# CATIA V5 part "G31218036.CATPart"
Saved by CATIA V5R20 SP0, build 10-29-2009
Part number: G31218036
Revision: 10
Definition: design
Nomenclature: G31218036
Source: made
Description: NOT SPECIFIED
Bounding box of the stored display mesh (mm): x -8 to 36, y -15.5 to 15.5, z -15.5 to 15.5
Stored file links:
  C:\Users\Raffaele\Desktop\3D X SITO CF\BOLEX\23-BUSH REF 312\G31218036.CATPart

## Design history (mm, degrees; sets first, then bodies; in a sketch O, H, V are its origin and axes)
Body1 "MANIFOLD_SOLID_BREP #10171" (main body)
  Solid1: solid without history
Body2 "MANIFOLD_SOLID_BREP #10314"
  Solid2: solid without history
Body3 "MANIFOLD_SOLID_BREP #10457"
  Solid3: solid without history
Body4 "MANIFOLD_SOLID_BREP #10600"
  Solid4: solid without history
Body5 "MANIFOLD_SOLID_BREP #10743"
  Solid5: solid without history
Body6 "MANIFOLD_SOLID_BREP #10888"
  Solid6: solid without history
Body7 "MANIFOLD_SOLID_BREP #11033"
  Solid7: solid without history
Body8 "MANIFOLD_SOLID_BREP #11178"
  Solid8: solid without history
Body9 "MANIFOLD_SOLID_BREP #11323"
  Solid9: solid without history
Body10 "MANIFOLD_SOLID_BREP #11468"
  Solid10: solid without history
Body11 "MANIFOLD_SOLID_BREP #11613"
  Solid11: solid without history
Body12 "MANIFOLD_SOLID_BREP #11758"
  Solid12: solid without history
Body13 "MANIFOLD_SOLID_BREP #11903"
  Solid13: solid without history
Body14 "MANIFOLD_SOLID_BREP #12048"
  Solid14: solid without history
Body15 "MANIFOLD_SOLID_BREP #12193"
  Solid15: solid without history
Body16 "MANIFOLD_SOLID_BREP #12338"
  Solid16: solid without history
Body17 "MANIFOLD_SOLID_BREP #12483"
  Solid17: solid without history
Body18 "MANIFOLD_SOLID_BREP #12630"
  Solid18: solid without history
Body19 "MANIFOLD_SOLID_BREP #12777"
  Solid19: solid without history
Body20 "MANIFOLD_SOLID_BREP #12924"
  Solid20: solid without history
Body21 "MANIFOLD_SOLID_BREP #13071"
  Solid21: solid without history
Body22 "MANIFOLD_SOLID_BREP #13216"
  Solid22: solid without history
Body23 "MANIFOLD_SOLID_BREP #13363"
  Solid23: solid without history
Body24 "MANIFOLD_SOLID_BREP #13510"
  Solid24: solid without history
Body25 "MANIFOLD_SOLID_BREP #13655"
  Solid25: solid without history
Body26 "MANIFOLD_SOLID_BREP #13800"
  Solid26: solid without history
Body27 "MANIFOLD_SOLID_BREP #13945"
  Solid27: solid without history
Body28 "MANIFOLD_SOLID_BREP #14090"
  Solid28: solid without history
Body29 "MANIFOLD_SOLID_BREP #14235"
  Solid29: solid without history
Body30 "MANIFOLD_SOLID_BREP #14380"
  Solid30: solid without history
Body31 "MANIFOLD_SOLID_BREP #14525"
  Solid31: solid without history
Body32 "MANIFOLD_SOLID_BREP #14668"
  Solid32: solid without history
Body33 "MANIFOLD_SOLID_BREP #14811"
  Solid33: solid without history
Body34 "MANIFOLD_SOLID_BREP #14958"
  Solid34: solid without history
Body35 "MANIFOLD_SOLID_BREP #15105"
  Solid35: solid without history
Body36 "MANIFOLD_SOLID_BREP #15252"
  Solid36: solid without history
Body37 "MANIFOLD_SOLID_BREP #15399"
  Solid37: solid without history
Body38 "MANIFOLD_SOLID_BREP #15544"
  Solid38: solid without history
Body39 "MANIFOLD_SOLID_BREP #15691"
  Solid39: solid without history
Body40 "MANIFOLD_SOLID_BREP #15838"
  Solid40: solid without history
Body41 "MANIFOLD_SOLID_BREP #15983"
  Solid41: solid without history
Body42 "MANIFOLD_SOLID_BREP #16128"
  Solid42: solid without history
Body43 "MANIFOLD_SOLID_BREP #16273"
  Solid43: solid without history
Body44 "MANIFOLD_SOLID_BREP #16418"
  Solid44: solid without history
Body45 "MANIFOLD_SOLID_BREP #16563"
  Solid45: solid without history
Body46 "MANIFOLD_SOLID_BREP #16708"
  Solid46: solid without history
Body47 "MANIFOLD_SOLID_BREP #16853"
  Solid47: solid without history
Body48 "MANIFOLD_SOLID_BREP #17000"
  Solid48: solid without history
Body49 "MANIFOLD_SOLID_BREP #17147"
  Solid49: solid without history
Body50 "MANIFOLD_SOLID_BREP #17294"
  Solid50: solid without history
Body51 "MANIFOLD_SOLID_BREP #17441"
  Solid51: solid without history
Body52 "MANIFOLD_SOLID_BREP #17586"
  Solid52: solid without history
Body53 "MANIFOLD_SOLID_BREP #17733"
  Solid53: solid without history
Body54 "MANIFOLD_SOLID_BREP #17880"
  Solid54: solid without history
Body55 "MANIFOLD_SOLID_BREP #18025"
  Solid55: solid without history
Body56 "MANIFOLD_SOLID_BREP #18168"
  Solid56: solid without history
Body57 "MANIFOLD_SOLID_BREP #18311"
  Solid57: solid without history
Body58 "MANIFOLD_SOLID_BREP #18456"
  Solid58: solid without history
Body59 "MANIFOLD_SOLID_BREP #18601"
  Solid59: solid without history
Body60 "MANIFOLD_SOLID_BREP #18746"
  Solid60: solid without history
Body61 "MANIFOLD_SOLID_BREP #18891"
  Solid61: solid without history
Body62 "MANIFOLD_SOLID_BREP #19036"
  Solid62: solid without history
Body63 "MANIFOLD_SOLID_BREP #19181"
  Solid63: solid without history
Body64 "MANIFOLD_SOLID_BREP #19324"
  Solid64: solid without history
Body65 "MANIFOLD_SOLID_BREP #19467"
  Solid65: solid without history
Body66 "MANIFOLD_SOLID_BREP #19614"
  Solid66: solid without history
Body67 "MANIFOLD_SOLID_BREP #19761"
  Solid67: solid without history
Body68 "MANIFOLD_SOLID_BREP #19908"
  Solid68: solid without history
Body69 "MANIFOLD_SOLID_BREP #20055"
  Solid69: solid without history
Body70 "MANIFOLD_SOLID_BREP #20200"
  Solid70: solid without history
Body71 "MANIFOLD_SOLID_BREP #20347"
  Solid71: solid without history
Body72 "MANIFOLD_SOLID_BREP #20494"
  Solid72: solid without history
Body73 "MANIFOLD_SOLID_BREP #20639"
  Solid73: solid without history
